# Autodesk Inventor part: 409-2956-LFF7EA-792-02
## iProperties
Shininess: 64.0
Angle Display Precision: 2
Document Length Units: 11272
Document Angle Units: 11279
Document Time Units: 11290
Document Mass Units: 11286
Document Length Units Precision: 3
Document Angle Units Precision: 2
Compacted: True
Created: 2002-04
Part Number: 409-2956-LFF7EA-792-02
Description: 2" PIPE MOUNT ANGLE
Document SubType Name: Modeling
Designer: S. Boerckel
Mass: 1123.41 g
Surface Area: 473.124 cm^2
Volume: 139.902 cm^3
Density: 8.03 g/cm^3
Cost Center: 3 x 3 x 1/4 ANGLE
Material: STAINLESS STEEL, 304
Engineer: S. Boerckel
Density: 0.0
Volumn: 0.0
Area: 0.0
PropertySet Name: Model Information
Control State: 0
Master: False
Checked Out: False
length: 6.000 in
SMR: =<COST CENTER> - <MATERIAL>
Author: S. Boerckel
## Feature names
1. Extrusion1
2. Hole1
